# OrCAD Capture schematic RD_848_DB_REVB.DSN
size B; title: DER-848 Daughter Board; rev: B
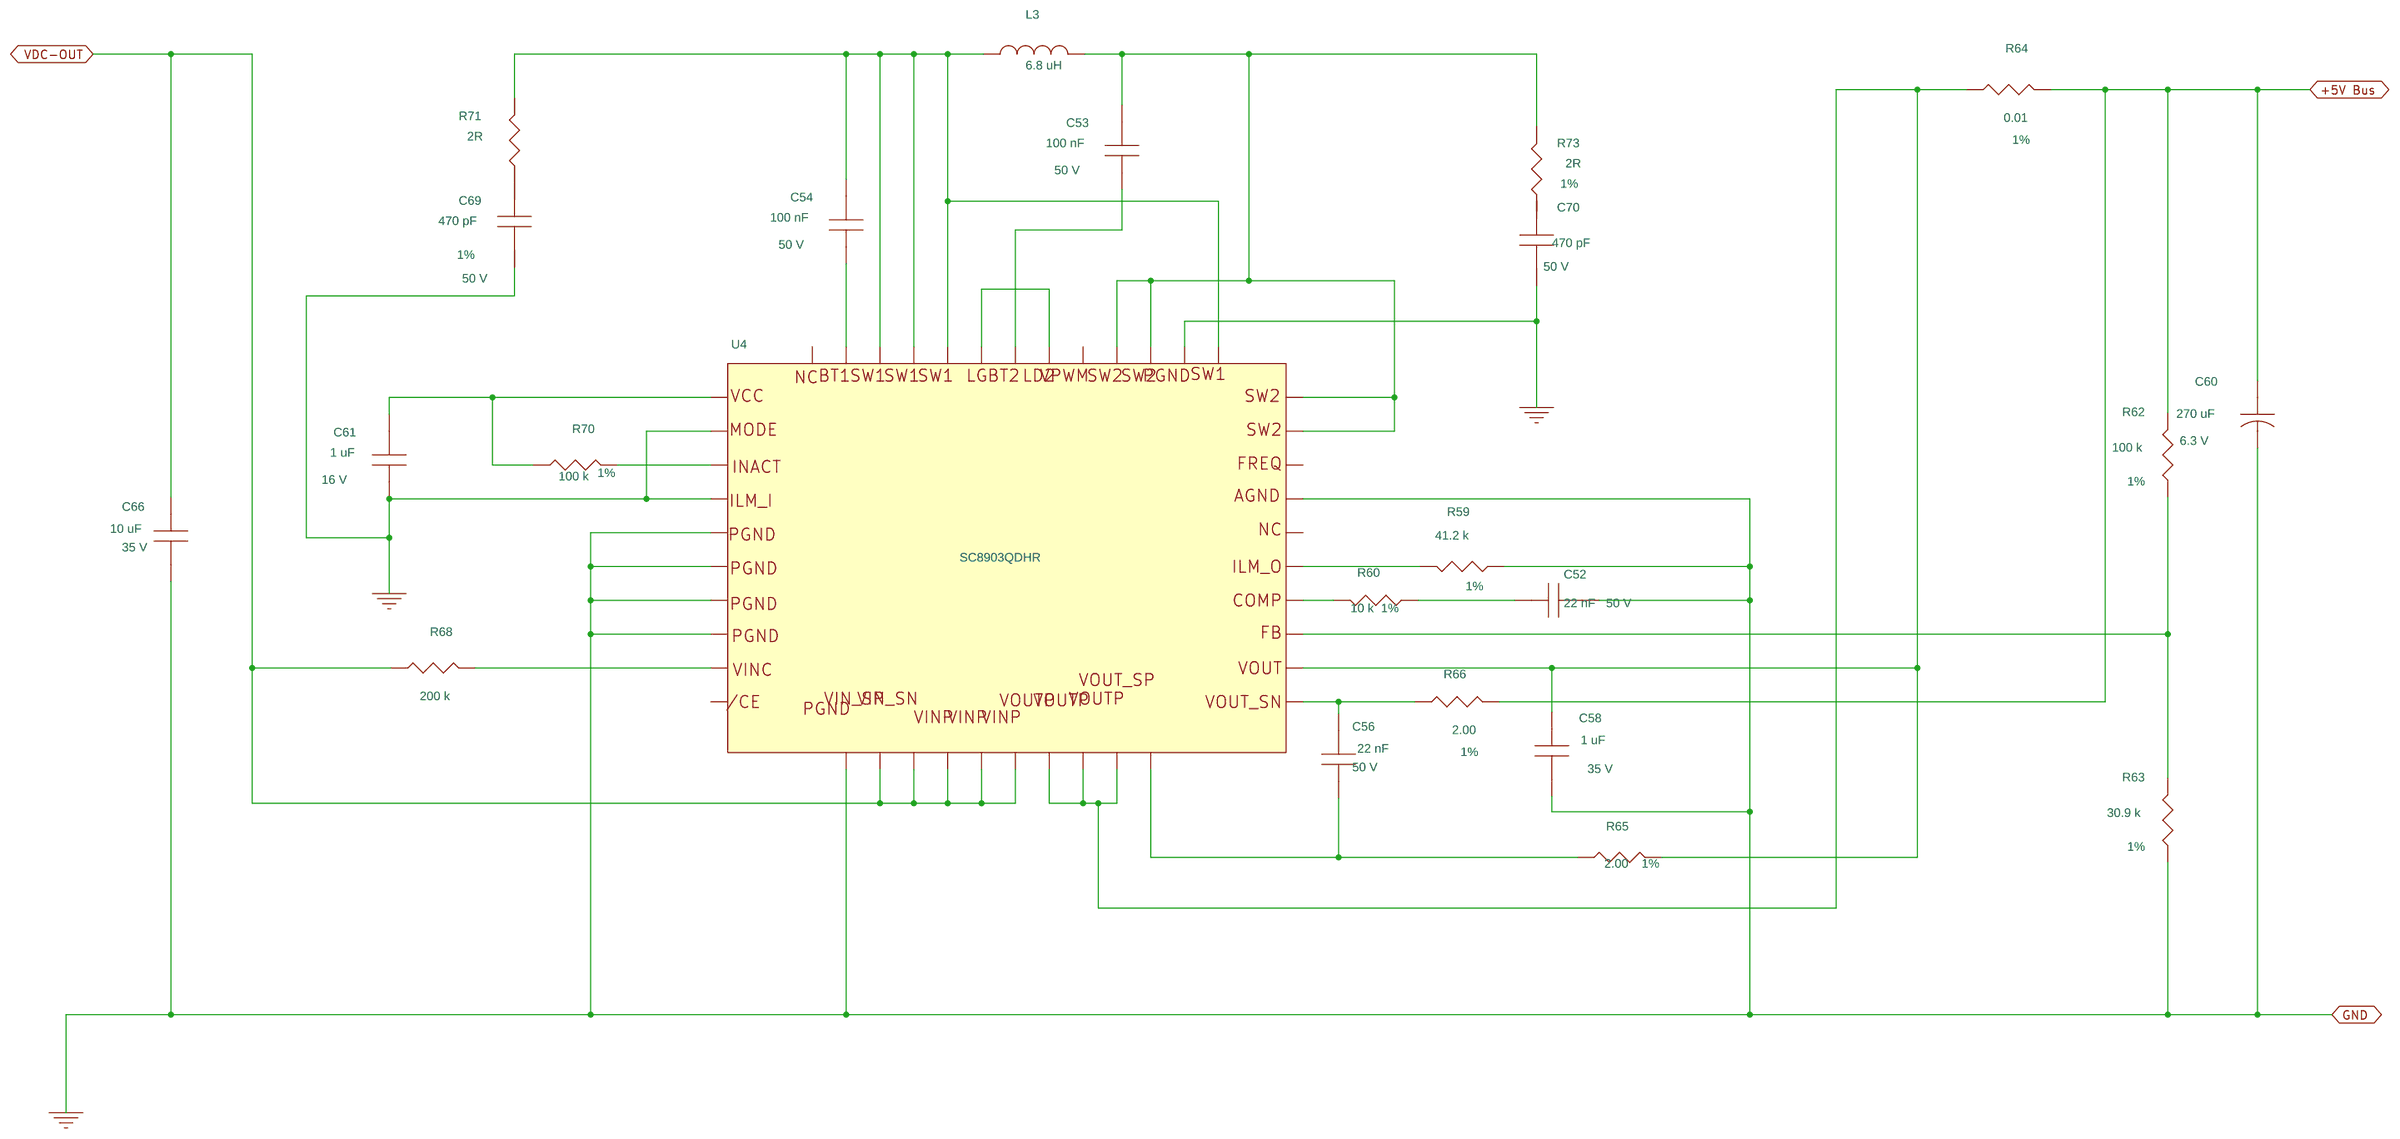
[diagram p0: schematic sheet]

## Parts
C52  22 nF  [pismc0603]
C53  100 nF  [pismc0603]
C54  100 nF  [pismc0603]
C56  22 nF  [pismc0603]
C58  1 uF  [pismc0603]
C60  270 uF  [pipolcapclyd200ls80030]
C61  1 uF  [pismc0603]
C66  10 uF  [pismc1206]
C69  470 pF  [pismc0603]
C70  470 pF  [pismc0603]
L3  6.8 uH  [pismind104CDMCCDS]
R59  41.2 k  [pismr0603]
R60  10 k  [pismr0603]
R62  100 k  [pismr0603]
R63  30.9 k  [pismr0603]
R64  0.01  [pismr0805]
R65  2.00  [pismr0603]
R66  2.00  [pismr0603]
R68  200 k  [pismr0402]
R70  100 k  [pismr0603]
R71  2R  [pismr0603]
R73  2R  [pismr0603]
U4  SC8903QDHR  [PI_SM_40QFN_3EP]

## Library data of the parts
C52 C56 = CAP_NP: Disp_Voltage: 50 V; Part Number: 20-01365-00; Room: Room3; Voltage: 50V
C53 C54 = CAP_NP: Disp_Voltage: 50 V; Part Number: 20-00936-00; Room: Room3; Voltage: 50 V
C58 = CAP_NP: ALT_SYMBOLS: pismc0603_1; Disp_Voltage: 35 V; FPLIST: pismc0603,pismc0603_1; Part Number: 20-09161-00; Voltage: 35 V
C60 = CAP_POL: Disp_Voltage: 6.3 V; Part Number: 20-01205-00; Voltage: 6.3V
C61 = CAP_NP: Disp_Voltage: 16 V; Part Number: 20-09157-00; Room: Room3; Voltage: 16 V
C66 = CAP_NP: ALT_SYMBOLS: pismc1206_1; Disp_Voltage: 35 V; FPLIST: pismc1206,pismc1206_1; Part Number: 20-09162-00; Voltage: 35 V
C69 C70 = CAP_NP: Disp_Voltage: 50 V; Part Number: 20-01359-00; Room: Room3; Voltage: 50 V
L3 = INDUCTOR: Part Number: 30-00502-00
R59 = R: Disp_Tol: 1%; Part Number: 05-03243-00
R60 R71 R73 = R: Disp_Tol: 1%; Part Number: 05-03182-00
R62 R70 = R: Disp_Tol: 1%; Part Number: 05-01174-00
R63 = R: Disp_Tol: 1%; Part Number: 05-03231-00
R64 = R: ALT_SYMBOLS: pismr0805_1; Disp_Tol: 1%; FPLIST: pismr0805,pismr0805_1; Part Number: 05-06341-00
R65 R66 = R: Disp_Tol: 1%; Part Number: 05-01277-00
R68 = R: Part Number: 05-06264-00
U4 = SC8903QDHR_1: Part Number: 45-00562-00

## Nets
+5V Bus: C60.1 R62.1 R64.1 R66.1
GND: C52.2 C58.2 C60.2 C61.1 C66.2 C69.2 C70.2 R59.2 R63.2 U4.4 U4.20 U4.23 U4.24 U4.25 U4.26 U4.27 U4.29 U4.42
VDC-OUT: C66.1 R68.2 U4.15 U4.16 U4.17 U4.18 U4.19
N12933668: C54.2 L3.2 R71.1 U4.33 U4.34 U4.35 U4.43
N12935088: R62.2 R63.1 U4.8
N12935357: C54.1 U4.32
N12935384: C53.2 L3.1 R73.1 U4.1 U4.2 U4.40 U4.41
N12935833: C56.1 R65.2 U4.11
N12936316: C58.1 R64.2 R65.1 U4.9 U4.12 U4.13 U4.14
N12938228: C61.2 R70.2 U4.30
N12938960: R59.1 U4.6
N12939085: R60.1 U4.7
N12943061: R68.1 U4.22
N12947202: C53.1 U4.37
N12951187: R70.1 U4.28
N12952491: U4.36 U4.38
N12999713: C70.1 R73.2
N13000797: C52.1 R60.2
N13002188: C56.2 R66.2 U4.10
N13009253: C69.1 R71.2

Not connected (* = marked no-connect by the designer): U4 3 5 21 31 39
